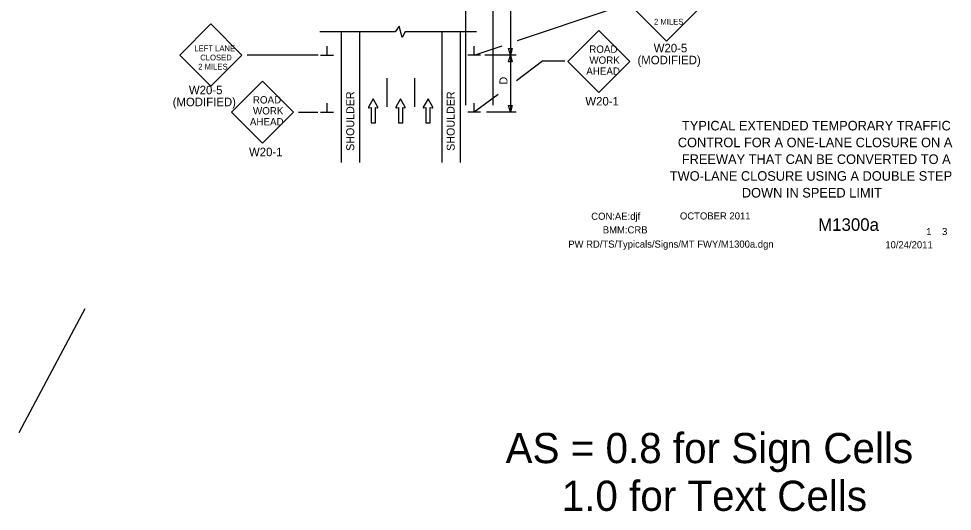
# Model space of a CAD drawing. Extents: x 16590 to 19508, y 5703 to 6974.
# Drawn here: x 16590 to 17407, y 5703 to 6134 of the extents above; entities that cross this region are included whole.
import ezdxf

# ---------------------------------------------------------------- set-up
doc = ezdxf.new("R2010")
doc.units = 0
for name, color, linetype in [('ALI_LEGAL_EX', 7, 'Continuous'), ('BORDER', 7, 'Continuous'), ('BORDER_SIGNAL_WO', 7, 'Continuous'), ('MT_SCRATCH_LEVEL_E', 7, 'Continuous'), ('PAVT_EDGE_EX', 7, 'Continuous'), ('TRAFFIC_SIGNS_PR', 7, 'Continuous'), ('TYPICAL_TEXT_DIMEN_PR', 7, 'Continuous')]:
    doc.layers.add(name, color=color, linetype=linetype)

msp = doc.modelspace()

# ---------------------------------------------------------------- linework, layer by layer
at = {"layer": 'ALI_LEGAL_EX'}
for p, q in [((16980.68, 6922.21), (16980.68, 6058.3)), ((17004.68, 6922.21), (17004.68, 6058.3))]:
    msp.add_line(p, q, dxfattribs=at)
for points in [[(16911.96, 6081.97), (16911.96, 6056.97)], [(16935.96, 6081.97), (16935.96, 6056.97)]]:
    msp.add_lwpolyline(points, dxfattribs=at)
at = {"layer": 'MT_SCRATCH_LEVEL_E'}
for p, q in [((16899.96, 6063.87), (16895.85, 6056.63)), ((16904.1, 6056.63), (16899.96, 6063.87)), ((16923.86, 6063.87), (16919.75, 6056.63)), ((16928.01, 6056.63), (16923.86, 6063.87)), ((16947.91, 6063.87), (16943.8, 6056.63)), ((16952.06, 6056.63), (16947.91, 6063.87)), ((16896.33, 6055.95), (16898.1, 6056.26)), ((16898.1, 6056.26), (16898.1, 6043.01)), ((16901.85, 6043.01), (16901.85, 6056.26)), ((16901.85, 6056.26), (16903.62, 6055.95)), ((16920.23, 6055.95), (16922.01, 6056.26)), ((16922.01, 6056.26), (16922.01, 6043.01)), ((16925.75, 6043.01), (16925.75, 6056.26)), ((16925.75, 6056.26), (16927.53, 6055.95)), ((16944.28, 6055.95), (16946.06, 6056.26)), ((16946.06, 6056.26), (16946.06, 6043.01)), ((16949.8, 6043.01), (16949.8, 6056.26)), ((16949.8, 6056.26), (16951.58, 6055.95)), ((16898.1, 6043.01), (16901.85, 6043.01)), ((16922.01, 6043.01), (16925.75, 6043.01)), ((16946.06, 6043.01), (16949.8, 6043.01))]:
    msp.add_line(p, q, dxfattribs=at)
for centre, start, end in [((16896.25, 6056.41), 150.42484, 279.96381), ((16903.69, 6056.41), 260.03619, 29.77312), ((16920.16, 6056.41), 150.42484, 279.96381), ((16927.6, 6056.41), 260.03619, 29.77312), ((16944.21, 6056.41), 150.42484, 279.96381), ((16951.65, 6056.41), 260.03619, 29.77312)]:
    msp.add_arc(centre, 0.463, start, end, dxfattribs=at)
at = {"layer": 'PAVT_EDGE_EX'}
for p, q in [((16871.96, 6122.63), (16871.96, 6008.06)), ((16887.96, 6122.63), (16887.96, 6008.06)), ((16959.96, 6122.63), (16959.96, 6008.06)), ((16975.96, 6122.63), (16975.96, 6008.06))]:
    msp.add_line(p, q, dxfattribs=at)
at = {"layer": 'TRAFFIC_SIGNS_PR'}
for p, q in [((17129.36, 6141.56), (17156.55, 6114.37)), ((17156.55, 6114.37), (17183.73, 6141.56)), ((16757.85, 6129.44), (16730.67, 6102.25)), ((16785.04, 6102.25), (16757.85, 6129.44)), ((17097.4, 6123.84), (17070.25, 6096.68)), ((17124.56, 6096.68), (17097.4, 6123.84)), ((16730.67, 6102.25), (16757.85, 6075.06)), ((16757.85, 6075.06), (16785.04, 6102.25)), ((17070.25, 6096.68), (17097.4, 6069.53)), ((17097.4, 6069.53), (17124.56, 6096.68)), ((16803.15, 6079.45), (16776, 6052.3)), ((16830.3, 6052.3), (16803.15, 6079.45)), ((16776, 6052.3), (16803.15, 6025.15)), ((16803.15, 6025.15), (16830.3, 6052.3))]:
    msp.add_line(p, q, dxfattribs=at)
at = {"layer": 'TYPICAL_TEXT_DIMEN_PR'}
for p, q in [((17019.96, 6202.2), (17019.96, 6102.2)), ((17026.2, 6114.95), (17106.39, 6141.93)), ((16922.56, 6127.43), (16919.31, 6122.63)), ((16925.3, 6117.49), (16922.56, 6127.43)), ((16919.31, 6122.63), (16853.36, 6122.63)), ((16928.05, 6122.63), (16925.3, 6117.49)), ((16990.38, 6122.63), (16928.05, 6122.63)), ((16859.58, 6102.2), (16859.58, 6109.99)), ((16988.33, 6102.2), (17012.74, 6110.42)), ((16988.33, 6102.2), (16988.33, 6109.99)), ((16851.75, 6102.2), (16789.63, 6102.2)), ((16853.96, 6102.2), (16865.21, 6102.2)), ((16993.96, 6102.2), (16982.71, 6102.2)), ((17024.96, 6102.2), (16997.63, 6102.2)), ((17019.96, 6102.2), (17018.39, 6108.07)), ((17018.39, 6108.07), (17019.96, 6108.07)), ((17018.39, 6096.34), (17019.96, 6102.2)), ((17019.96, 6108.07), (17021.53, 6108.07)), ((17021.53, 6108.07), (17019.96, 6102.2)), ((17019.96, 6102.2), (17019.96, 6052.2)), ((17019.96, 6102.2), (17021.53, 6096.34)), ((17019.96, 6096.34), (17018.39, 6096.34)), ((17021.53, 6096.34), (17019.96, 6096.34)), ((17048.47, 6097.09), (17025.3, 6079.8)), ((17048.47, 6097.09), (17067.66, 6097.09)), ((17009.3, 6067.86), (16988.33, 6052.2)), ((16834.48, 6052.2), (16851.48, 6052.2)), ((16853.96, 6052.2), (16865.21, 6052.2)), ((16859.58, 6052.2), (16859.58, 6059.99)), ((16993.96, 6052.2), (16982.71, 6052.2)), ((16988.33, 6052.2), (16988.33, 6059.99)), ((17024.96, 6052.2), (16998.96, 6052.2)), ((17019.96, 6052.2), (17018.39, 6058.07)), ((17018.39, 6058.07), (17019.96, 6058.07)), ((17019.96, 6058.07), (17021.53, 6058.07)), ((17021.53, 6058.07), (17019.96, 6052.2)), ((16647.75, 5880), (16589.83, 5771.74))]:
    msp.add_line(p, q, dxfattribs=at)

# ---------------------------------------------------------------- texts
at = {"layer": 'BORDER'}
for s, p in [('TYPICAL EXTENDED TEMPORARY TRAFFIC', (17170.06, 6036.26)), ('CONTROL FOR A ONE-LANE CLOSURE ON A', (17166.43, 6021.59)), ('FREEWAY THAT CAN BE CONVERTED TO A', (17169.93, 6006.91)), ('TWO-LANE CLOSURE USING A DOUBLE STEP ', (17159.43, 5992.23)), ('DOWN IN SPEED LIMIT', (17222.43, 5977.56))]:
    msp.add_text(s, height=8.3734, dxfattribs=at).set_placement(p)
at = {"layer": 'BORDER_SIGNAL_WO'}
for s, height, p in [('CON:AE:djf  ', 6.2, (17090.69, 5958.06)), ('    OCTOBER 2011    ', 6.2, (17159.08, 5958.34)), ('    M1300a   ', 11, (17272.86, 5948.38)), ('BMM:CRB   ', 6.2, (17100.81, 5946.17)), (' 1    3 ', 6.2, (17381.45, 5944.7)), ('PW RD/TS/Typicals/Signs/MT FWY/M1300a.dgn      ', 6.2, (17070.55, 5933.71)), ('10/24/2011    ', 6.2, (17347.93, 5933.13)), ('AS = 0.8 for Sign Cells', 26.4241, (17015.79, 5745.09)), ('     1.0 for Text Cells', 26.4241, (17015.79, 5703.3))]:
    msp.add_text(s, height=height, dxfattribs=at).set_placement(p)
at = {"layer": 'TRAFFIC_SIGNS_PR'}
for s, height, p in [('2 MILES', 5.006, (17145.62, 6128.9)), ('LEFT LANE', 5.006, (16743.46, 6105.6)), ('ROAD', 6.4, (17088.94, 6104.22)), ('W20-5', 7.449, (17145.34, 6104.61)), ('CLOSED', 5.006, (16748.68, 6097.59)), ('WORK', 6.4, (17089.05, 6094.62)), ('(MODIFIED)', 7.449, (17131.15, 6094.16)), ('2 MILES', 5.006, (16746.92, 6089.58)), ('AHEAD', 6.4, (17086.36, 6085.02)), ('W20-5', 7.449, (16738.75, 6067.91)), ('(MODIFIED)', 7.449, (16724.55, 6057.46)), ('ROAD', 6.4, (16794.69, 6059.84)), ('W20-1', 7.44, (17085.57, 6058.09)), ('WORK', 6.4, (16794.8, 6050.24)), ('AHEAD', 6.4, (16792.11, 6040.64)), ('W20-1', 7.44, (16791.32, 6013.71))]:
    msp.add_text(s, height=height, dxfattribs=at).set_placement(p)
at = {"layer": 'TYPICAL_TEXT_DIMEN_PR'}
for s, p in [('D', (17017.4, 6076.42)), ('SHOULDER', (16883.38, 6018.42)), ('SHOULDER', (16971.24, 6018.42))]:
    msp.add_text(s, height=7, rotation=90, dxfattribs=at).set_placement(p)

doc.saveas('drawing.dxf')
